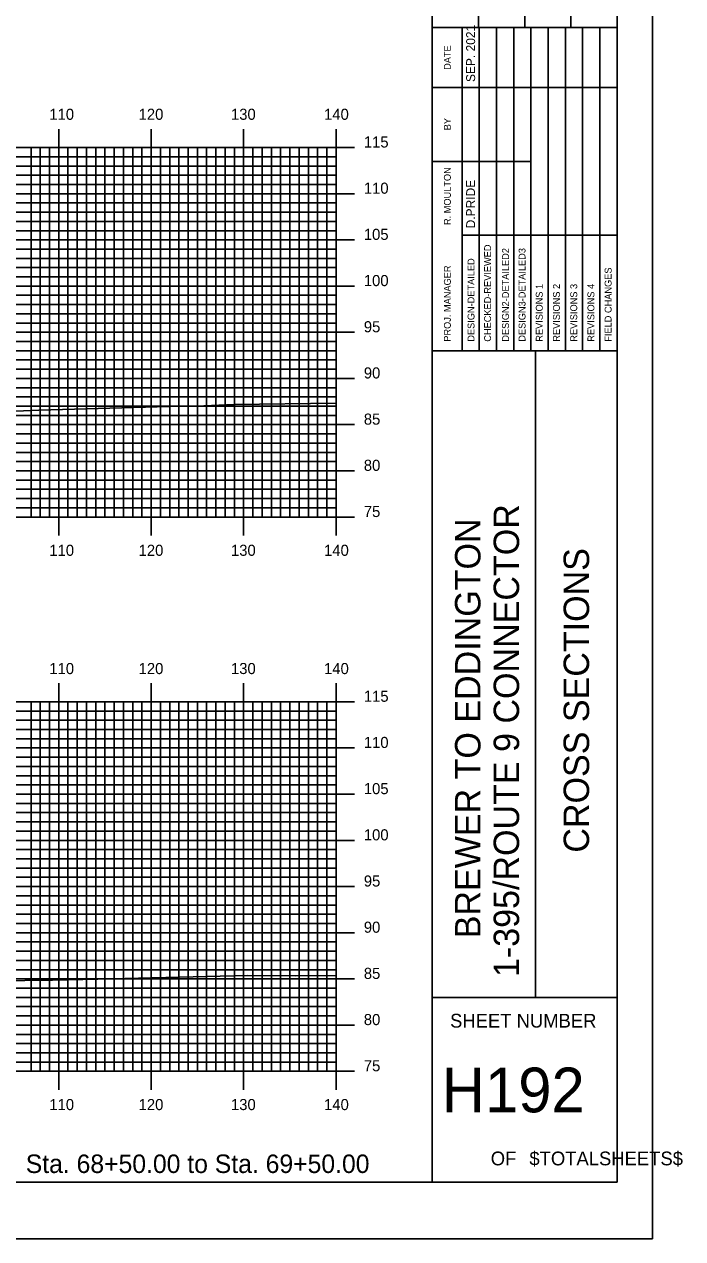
# Model space of a CAD drawing. Extents: x 1759823 to 1760167, y 442591 to 442811.
# Drawn here: x 1760095.5 to 1760166.7, y 442590.5 to 442722 of the extents above; entities that cross this region are included whole.
import ezdxf

# ---------------------------------------------------------------- set-up
doc = ezdxf.new("R2010")
doc.units = 0
for name, color, linetype in [('BORDER', 7, 'Continuous'), ('H_V ANNOTATION', 7, 'Continuous'), ('MAJOR', 7, 'Continuous'), ('MINOR', 7, 'Continuous'), ('PLOT BOUNDARY', 7, 'Continuous'), ('S_Roadway_Centerline', 7, 'Continuous')]:
    doc.layers.add(name, color=color, linetype=linetype)

msp = doc.modelspace()

# ---------------------------------------------------------------- linework, layer by layer
at = {"layer": 'BORDER'}
for p, q in [((1760139.59, 442596.67), (1760139.59, 442806.67)), ((1760144.59, 442721.67), (1760144.59, 442738.97)), ((1760149.59, 442721.67), (1760149.59, 442738.97)), ((1760154.59, 442721.67), (1760154.59, 442738.97)), ((1760139.59, 442721.67), (1760159.59, 442721.67)), ((1760139.59, 442686.67), (1760159.59, 442686.67)), ((1760150.77, 442616.67), (1760150.77, 442686.67)), ((1760139.59, 442616.67), (1760159.59, 442616.67))]:
    msp.add_line(p, q, dxfattribs=at)
msp.add_lwpolyline([(1759839.59, 442596.67), (1760159.59, 442596.67), (1760159.59, 442806.67), (1759839.59, 442806.67)], close=True, dxfattribs=at)
for points in [[(1760142.82, 442715.17), (1760142.82, 442721.67)], [(1760144.68, 442686.68), (1760144.68, 442721.67)], [(1760146.55, 442721.67), (1760146.55, 442686.68)], [(1760148.41, 442686.68), (1760148.41, 442721.67)], [(1760150.27, 442686.68), (1760150.27, 442721.67)], [(1760152.14, 442686.68), (1760152.14, 442721.67)], [(1760154, 442686.68), (1760154, 442721.67)], [(1760155.86, 442686.68), (1760155.86, 442721.67)], [(1760157.73, 442686.68), (1760157.73, 442721.67)], [(1760142.82, 442686.68), (1760142.82, 442720.26)], [(1760139.59, 442715.17), (1760159.59, 442715.17)], [(1760139.59, 442707.17), (1760142.82, 442707.17)], [(1760142.82, 442707.17), (1760150.27, 442707.17)], [(1760142.82, 442699.17), (1760159.59, 442699.17)]]:
    msp.add_lwpolyline(points, dxfattribs=at)
at = {"layer": 'MAJOR'}
for p, q in [((1760099.19, 442710.67), (1760099.19, 442708.67)), ((1760109.19, 442710.67), (1760109.19, 442708.67)), ((1760119.19, 442710.67), (1760119.19, 442708.67)), ((1760129.19, 442710.67), (1760129.19, 442708.67)), ((1759849.19, 442708.67), (1760129.19, 442708.67)), ((1759849.19, 442708.67), (1760129.19, 442708.67)), ((1760099.19, 442668.67), (1760099.19, 442708.67)), ((1760109.19, 442668.67), (1760109.19, 442708.67)), ((1760119.19, 442668.67), (1760119.19, 442708.67)), ((1760131.19, 442708.67), (1760127.18, 442708.67)), ((1760129.19, 442668.67), (1760129.19, 442708.67)), ((1760129.19, 442668.67), (1760129.19, 442708.67)), ((1759849.19, 442703.67), (1760129.19, 442703.67)), ((1760131.19, 442703.67), (1760127.18, 442703.67)), ((1759849.19, 442698.67), (1760129.19, 442698.67)), ((1760131.19, 442698.67), (1760127.18, 442698.67)), ((1759849.19, 442693.67), (1760129.19, 442693.67)), ((1760131.19, 442693.67), (1760127.18, 442693.67)), ((1759849.19, 442688.67), (1760129.19, 442688.67)), ((1760131.19, 442688.67), (1760127.18, 442688.67)), ((1759849.19, 442683.67), (1760129.19, 442683.67)), ((1760131.19, 442683.67), (1760127.18, 442683.67)), ((1759849.19, 442678.67), (1760129.19, 442678.67)), ((1760131.19, 442678.67), (1760127.18, 442678.67)), ((1759849.19, 442673.67), (1760129.19, 442673.67)), ((1760131.19, 442673.67), (1760127.18, 442673.67)), ((1759849.19, 442668.67), (1760129.19, 442668.67)), ((1759849.19, 442668.67), (1760129.19, 442668.67)), ((1760099.19, 442666.66), (1760099.19, 442668.67)), ((1760109.19, 442666.66), (1760109.19, 442668.67)), ((1760119.19, 442666.66), (1760119.19, 442668.67)), ((1760131.19, 442668.67), (1760127.18, 442668.67)), ((1760129.19, 442666.66), (1760129.19, 442668.67)), ((1760099.19, 442650.67), (1760099.19, 442648.67)), ((1760109.19, 442650.67), (1760109.19, 442648.67)), ((1760119.19, 442650.67), (1760119.19, 442648.67)), ((1760129.19, 442650.67), (1760129.19, 442648.67)), ((1759849.19, 442648.67), (1760129.19, 442648.67)), ((1759849.19, 442648.67), (1760129.19, 442648.67)), ((1760099.19, 442608.67), (1760099.19, 442648.67)), ((1760109.19, 442608.67), (1760109.19, 442648.67)), ((1760119.19, 442608.67), (1760119.19, 442648.67)), ((1760131.19, 442648.67), (1760127.18, 442648.67)), ((1760129.19, 442608.67), (1760129.19, 442648.67)), ((1760129.19, 442608.67), (1760129.19, 442648.67)), ((1759849.19, 442643.67), (1760129.19, 442643.67)), ((1760131.19, 442643.67), (1760127.18, 442643.67)), ((1759849.19, 442638.67), (1760129.19, 442638.67)), ((1760131.19, 442638.67), (1760127.18, 442638.67)), ((1759849.19, 442633.67), (1760129.19, 442633.67)), ((1760131.19, 442633.67), (1760127.18, 442633.67)), ((1759849.19, 442628.67), (1760129.19, 442628.67)), ((1760131.19, 442628.67), (1760127.18, 442628.67)), ((1759849.19, 442623.67), (1760129.19, 442623.67)), ((1760131.19, 442623.67), (1760127.18, 442623.67)), ((1759849.19, 442618.67), (1760129.19, 442618.67)), ((1760131.19, 442618.67), (1760127.18, 442618.67)), ((1759849.19, 442613.67), (1760129.19, 442613.67)), ((1760131.19, 442613.67), (1760127.18, 442613.67)), ((1759849.19, 442608.67), (1760129.19, 442608.67)), ((1759849.19, 442608.67), (1760129.19, 442608.67)), ((1760099.19, 442606.66), (1760099.19, 442608.67)), ((1760109.19, 442606.66), (1760109.19, 442608.67)), ((1760119.19, 442606.66), (1760119.19, 442608.67)), ((1760131.19, 442608.67), (1760127.18, 442608.67)), ((1760129.19, 442606.66), (1760129.19, 442608.67))]:
    msp.add_line(p, q, dxfattribs=at)
at = {"layer": 'MINOR'}
for p, q in [((1760096.19, 442668.67), (1760096.19, 442708.67)), ((1760097.19, 442668.67), (1760097.19, 442708.67)), ((1760098.19, 442668.67), (1760098.19, 442708.67)), ((1760100.19, 442668.67), (1760100.19, 442708.67)), ((1760101.19, 442668.67), (1760101.19, 442708.67)), ((1760102.19, 442668.67), (1760102.19, 442708.67)), ((1760103.19, 442668.67), (1760103.19, 442708.67)), ((1760104.19, 442668.67), (1760104.19, 442708.67)), ((1760105.19, 442668.67), (1760105.19, 442708.67)), ((1760106.19, 442668.67), (1760106.19, 442708.67)), ((1760107.19, 442668.67), (1760107.19, 442708.67)), ((1760108.19, 442668.67), (1760108.19, 442708.67)), ((1760110.19, 442668.67), (1760110.19, 442708.67)), ((1760111.19, 442668.67), (1760111.19, 442708.67)), ((1760112.19, 442668.67), (1760112.19, 442708.67)), ((1760113.19, 442668.67), (1760113.19, 442708.67)), ((1760114.19, 442668.67), (1760114.19, 442708.67)), ((1760115.19, 442668.67), (1760115.19, 442708.67)), ((1760116.19, 442668.67), (1760116.19, 442708.67)), ((1760117.19, 442668.67), (1760117.19, 442708.67)), ((1760118.19, 442668.67), (1760118.19, 442708.67)), ((1760120.19, 442668.67), (1760120.19, 442708.67)), ((1760121.19, 442668.67), (1760121.19, 442708.67)), ((1760122.19, 442668.67), (1760122.19, 442708.67)), ((1760123.19, 442668.67), (1760123.19, 442708.67)), ((1760124.19, 442668.67), (1760124.19, 442708.67)), ((1760125.19, 442668.67), (1760125.19, 442708.67)), ((1760126.19, 442668.67), (1760126.19, 442708.67)), ((1760127.19, 442668.67), (1760127.19, 442708.67)), ((1760128.19, 442668.67), (1760128.19, 442708.67)), ((1759849.19, 442707.67), (1760129.19, 442707.67)), ((1760129.19, 442707.67), (1760127.18, 442707.67)), ((1759849.19, 442706.67), (1760129.19, 442706.67)), ((1759849.19, 442705.67), (1760129.19, 442705.67)), ((1760129.19, 442706.67), (1760127.18, 442706.67)), ((1760129.19, 442705.67), (1760127.18, 442705.67)), ((1759849.19, 442704.67), (1760129.19, 442704.67)), ((1760129.19, 442704.67), (1760127.18, 442704.67)), ((1759849.19, 442702.67), (1760129.19, 442702.67)), ((1759849.19, 442701.67), (1760129.19, 442701.67)), ((1760129.19, 442702.67), (1760127.18, 442702.67)), ((1760129.19, 442701.67), (1760127.18, 442701.67)), ((1759849.19, 442700.67), (1760129.19, 442700.67)), ((1760129.19, 442700.67), (1760127.18, 442700.67)), ((1759849.19, 442699.67), (1760129.19, 442699.67)), ((1760129.19, 442699.67), (1760127.18, 442699.67)), ((1759849.19, 442697.67), (1760129.19, 442697.67)), ((1760129.19, 442697.67), (1760127.18, 442697.67)), ((1759849.19, 442696.67), (1760129.19, 442696.67)), ((1760129.19, 442696.67), (1760127.18, 442696.67)), ((1759849.19, 442695.67), (1760129.19, 442695.67)), ((1760129.19, 442695.67), (1760127.18, 442695.67)), ((1759849.19, 442694.67), (1760129.19, 442694.67)), ((1760129.19, 442694.67), (1760127.18, 442694.67)), ((1759849.19, 442692.67), (1760129.19, 442692.67)), ((1760129.19, 442692.67), (1760127.18, 442692.67)), ((1759849.19, 442691.67), (1760129.19, 442691.67)), ((1760129.19, 442691.67), (1760127.18, 442691.67)), ((1759849.19, 442690.67), (1760129.19, 442690.67)), ((1760129.19, 442690.67), (1760127.18, 442690.67)), ((1759849.19, 442689.67), (1760129.19, 442689.67)), ((1760129.19, 442689.67), (1760127.18, 442689.67)), ((1759849.19, 442687.67), (1760129.19, 442687.67)), ((1760129.19, 442687.67), (1760127.18, 442687.67)), ((1759849.19, 442686.67), (1760129.19, 442686.67)), ((1760129.19, 442686.67), (1760127.18, 442686.67)), ((1759849.19, 442685.67), (1760129.19, 442685.67)), ((1759849.19, 442684.67), (1760129.19, 442684.67)), ((1760129.19, 442685.67), (1760127.18, 442685.67)), ((1760129.19, 442684.67), (1760127.18, 442684.67)), ((1759849.19, 442682.67), (1760129.19, 442682.67)), ((1760129.19, 442682.67), (1760127.18, 442682.67)), ((1759849.19, 442681.67), (1760129.19, 442681.67)), ((1759849.19, 442680.67), (1760129.19, 442680.67)), ((1760129.19, 442681.67), (1760127.18, 442681.67)), ((1760129.19, 442680.67), (1760127.18, 442680.67)), ((1759849.19, 442679.67), (1760129.19, 442679.67)), ((1760129.19, 442679.67), (1760127.18, 442679.67)), ((1759849.19, 442677.67), (1760129.19, 442677.67)), ((1759849.19, 442676.67), (1760129.19, 442676.67)), ((1760129.19, 442677.67), (1760127.18, 442677.67)), ((1760129.19, 442676.67), (1760127.18, 442676.67)), ((1759849.19, 442675.67), (1760129.19, 442675.67)), ((1760129.19, 442675.67), (1760127.18, 442675.67)), ((1759849.19, 442674.67), (1760129.19, 442674.67)), ((1760129.19, 442674.67), (1760127.18, 442674.67)), ((1759849.19, 442672.67), (1760129.19, 442672.67)), ((1760129.19, 442672.67), (1760127.18, 442672.67)), ((1759849.19, 442671.67), (1760129.19, 442671.67)), ((1760129.19, 442671.67), (1760127.18, 442671.67)), ((1759849.19, 442670.67), (1760129.19, 442670.67)), ((1760129.19, 442670.67), (1760127.18, 442670.67)), ((1759849.19, 442669.67), (1760129.19, 442669.67)), ((1760129.19, 442669.67), (1760127.18, 442669.67)), ((1759849.19, 442647.67), (1760129.19, 442647.67)), ((1760096.19, 442608.67), (1760096.19, 442648.67)), ((1760097.19, 442608.67), (1760097.19, 442648.67)), ((1760098.19, 442608.67), (1760098.19, 442648.67)), ((1760100.19, 442608.67), (1760100.19, 442648.67)), ((1760101.19, 442608.67), (1760101.19, 442648.67)), ((1760102.19, 442608.67), (1760102.19, 442648.67)), ((1760103.19, 442608.67), (1760103.19, 442648.67)), ((1760104.19, 442608.67), (1760104.19, 442648.67)), ((1760105.19, 442608.67), (1760105.19, 442648.67)), ((1760106.19, 442608.67), (1760106.19, 442648.67)), ((1760107.19, 442608.67), (1760107.19, 442648.67)), ((1760108.19, 442608.67), (1760108.19, 442648.67)), ((1760110.19, 442608.67), (1760110.19, 442648.67)), ((1760111.19, 442608.67), (1760111.19, 442648.67)), ((1760112.19, 442608.67), (1760112.19, 442648.67)), ((1760113.19, 442608.67), (1760113.19, 442648.67)), ((1760114.19, 442608.67), (1760114.19, 442648.67)), ((1760115.19, 442608.67), (1760115.19, 442648.67)), ((1760116.19, 442608.67), (1760116.19, 442648.67)), ((1760117.19, 442608.67), (1760117.19, 442648.67)), ((1760118.19, 442608.67), (1760118.19, 442648.67)), ((1760120.19, 442608.67), (1760120.19, 442648.67)), ((1760121.19, 442608.67), (1760121.19, 442648.67)), ((1760122.19, 442608.67), (1760122.19, 442648.67)), ((1760123.19, 442608.67), (1760123.19, 442648.67)), ((1760124.19, 442608.67), (1760124.19, 442648.67)), ((1760125.19, 442608.67), (1760125.19, 442648.67)), ((1760126.19, 442608.67), (1760126.19, 442648.67)), ((1760129.19, 442647.67), (1760127.18, 442647.67)), ((1760127.19, 442608.67), (1760127.19, 442648.67)), ((1760128.19, 442608.67), (1760128.19, 442648.67)), ((1759849.19, 442646.67), (1760129.19, 442646.67)), ((1760129.19, 442646.67), (1760127.18, 442646.67)), ((1759849.19, 442645.67), (1760129.19, 442645.67)), ((1760129.19, 442645.67), (1760127.18, 442645.67)), ((1759849.19, 442644.67), (1760129.19, 442644.67)), ((1760129.19, 442644.67), (1760127.18, 442644.67)), ((1759849.19, 442642.67), (1760129.19, 442642.67)), ((1760129.19, 442642.67), (1760127.18, 442642.67)), ((1759849.19, 442641.67), (1760129.19, 442641.67)), ((1760129.19, 442641.67), (1760127.18, 442641.67)), ((1759849.19, 442640.67), (1760129.19, 442640.67)), ((1760129.19, 442640.67), (1760127.18, 442640.67)), ((1759849.19, 442639.67), (1760129.19, 442639.67)), ((1760129.19, 442639.67), (1760127.18, 442639.67)), ((1759849.19, 442637.67), (1760129.19, 442637.67)), ((1760129.19, 442637.67), (1760127.18, 442637.67)), ((1759849.19, 442636.67), (1760129.19, 442636.67)), ((1760129.19, 442636.67), (1760127.18, 442636.67)), ((1759849.19, 442635.67), (1760129.19, 442635.67)), ((1759849.19, 442634.67), (1760129.19, 442634.67)), ((1760129.19, 442635.67), (1760127.18, 442635.67)), ((1760129.19, 442634.67), (1760127.18, 442634.67)), ((1759849.19, 442632.67), (1760129.19, 442632.67)), ((1760129.19, 442632.67), (1760127.18, 442632.67)), ((1759849.19, 442631.67), (1760129.19, 442631.67)), ((1759849.19, 442630.67), (1760129.19, 442630.67)), ((1760129.19, 442631.67), (1760127.18, 442631.67)), ((1760129.19, 442630.67), (1760127.18, 442630.67)), ((1759849.19, 442629.67), (1760129.19, 442629.67)), ((1760129.19, 442629.67), (1760127.18, 442629.67)), ((1759849.19, 442627.67), (1760129.19, 442627.67)), ((1759849.19, 442626.67), (1760129.19, 442626.67)), ((1760129.19, 442627.67), (1760127.18, 442627.67)), ((1760129.19, 442626.67), (1760127.18, 442626.67)), ((1759849.19, 442625.67), (1760129.19, 442625.67)), ((1760129.19, 442625.67), (1760127.18, 442625.67)), ((1759849.19, 442624.67), (1760129.19, 442624.67)), ((1760129.19, 442624.67), (1760127.18, 442624.67)), ((1759849.19, 442622.67), (1760129.19, 442622.67)), ((1760129.19, 442622.67), (1760127.18, 442622.67)), ((1759849.19, 442621.67), (1760129.19, 442621.67)), ((1760129.19, 442621.67), (1760127.18, 442621.67)), ((1759849.19, 442620.67), (1760129.19, 442620.67)), ((1760129.19, 442620.67), (1760127.18, 442620.67)), ((1759849.19, 442619.67), (1760129.19, 442619.67)), ((1760129.19, 442619.67), (1760127.18, 442619.67)), ((1759849.19, 442617.67), (1760129.19, 442617.67)), ((1760129.19, 442617.67), (1760127.18, 442617.67)), ((1759849.19, 442616.67), (1760129.19, 442616.67)), ((1760129.19, 442616.67), (1760127.18, 442616.67)), ((1759849.19, 442615.67), (1760129.19, 442615.67)), ((1760129.19, 442615.67), (1760127.18, 442615.67)), ((1759849.19, 442614.67), (1760129.19, 442614.67)), ((1760129.19, 442614.67), (1760127.18, 442614.67)), ((1759849.19, 442612.67), (1760129.19, 442612.67)), ((1760129.19, 442612.67), (1760127.18, 442612.67)), ((1759849.19, 442611.67), (1760129.19, 442611.67)), ((1760129.19, 442611.67), (1760127.18, 442611.67)), ((1759849.19, 442610.67), (1760129.19, 442610.67)), ((1759849.19, 442609.67), (1760129.19, 442609.67)), ((1760129.19, 442610.67), (1760127.18, 442610.67)), ((1760129.19, 442609.67), (1760127.18, 442609.67))]:
    msp.add_line(p, q, dxfattribs=at)
at = {"layer": 'PLOT BOUNDARY'}
msp.add_lwpolyline([(1759823.4, 442590.55), (1760163.4, 442590.55), (1760163.4, 442810.55), (1759823.4, 442810.55)], close=True, dxfattribs=at)
at = {"layer": 'S_Roadway_Centerline'}
for points in [[(1760021.92, 442677.99), (1760032.85, 442678.42), (1760033.94, 442678.46), (1760034.82, 442678.49), (1760045.31, 442678.69), (1760055.22, 442679.36), (1760059.66, 442679.52), (1760076.74, 442679.65), (1760080.19, 442679.7), (1760085.5, 442679.88), (1760092.06, 442680.03), (1760097.04, 442680.25), (1760111.13, 442680.63), (1760114.9, 442680.71), (1760118.12, 442680.84), (1760129.19, 442680.98)], [(1760018.12, 442616.64), (1760028.47, 442616.89), (1760036.49, 442617.09), (1760044, 442617.36), (1760056.97, 442617.66), (1760063.01, 442617.61), (1760071.47, 442617.83), (1760077.81, 442618.21), (1760097.71, 442618.55), (1760098.53, 442618.52), (1760103.41, 442618.63), (1760119.61, 442619.04), (1760124.83, 442618.99), (1760129.19, 442619.03)]]:
    msp.add_lwpolyline(points, dxfattribs=at)

# ---------------------------------------------------------------- texts
at = {"layer": 'BORDER'}
for s, height, p in [('SEP. 2021', 0.969, (1760144.23, 442715.76)), ('DATE', 0.743, (1760141.6, 442717.08)), ('BY', 0.743, (1760141.6, 442710.54)), ('R. MOULTON', 0.745, (1760141.6, 442700.28)), ('D.PRIDE', 0.969, (1760144.23, 442699.92)), ('CHECKED-REVIEWED', 0.7455, (1760145.95, 442687.65)), ('DESIGN2-DETAILED2', 0.7455, (1760147.89, 442687.65)), ('DESIGN3-DETAILED3', 0.7455, (1760149.68, 442687.65)), ('DESIGN-DETAILED', 0.7455, (1760144.16, 442687.65)), ('PROJ. MANAGER', 0.7455, (1760141.6, 442687.65)), ('FIELD CHANGES', 0.7455, (1760158.99, 442687.65)), ('REVISIONS 1', 0.7455, (1760151.54, 442687.65)), ('REVISIONS 2', 0.7455, (1760153.4, 442687.65)), ('REVISIONS 3', 0.7455, (1760155.27, 442687.65)), ('REVISIONS 4', 0.7455, (1760157.13, 442687.65)), ('1-395/ROUTE 9 CONNECTOR', 2.7557, (1760148.99, 442618.87)), ('BREWER TO EDDINGTON', 2.7557, (1760144.81, 442623.07)), ('CROSS SECTIONS', 2.7557, (1760156.56, 442632.34))]:
    msp.add_text(s, height=height, rotation=90, dxfattribs=at).set_placement(p)
for s, height, p in [('SHEET NUMBER', 1.4905, (1760141.52, 442613.4)), ('H192', 4.839, (1760140.62, 442604.23)), ('OF', 1.491, (1760145.92, 442598.49)), ('$TOTALSHEETS$', 1.4905, (1760150.1, 442598.49))]:
    msp.add_text(s, height=height, dxfattribs=at).set_placement(p)
at = {"layer": 'H_V ANNOTATION'}
for s, height, p in [('110', 1.2, (1760098.17, 442711.67)), ('120', 1.2, (1760107.83, 442711.67)), ('130', 1.2, (1760117.82, 442711.67)), ('140', 1.2, (1760127.89, 442711.67)), ('115', 1.2, (1760132.19, 442708.67)), ('110', 1.2, (1760132.19, 442703.67)), ('105', 1.2, (1760132.19, 442698.67)), ('100', 1.2, (1760132.19, 442693.67)), ('95', 1.2, (1760132.19, 442688.67)), ('90', 1.2, (1760132.19, 442683.67)), ('85', 1.2, (1760132.19, 442678.67)), ('80', 1.2, (1760132.19, 442673.67)), ('75', 1.2, (1760132.19, 442668.67)), ('110', 1.2, (1760098.17, 442664.47)), ('120', 1.2, (1760107.83, 442664.47)), ('130', 1.2, (1760117.82, 442664.47)), ('140', 1.2, (1760127.89, 442664.47)), ('110', 1.2, (1760098.17, 442651.67)), ('120', 1.2, (1760107.83, 442651.67)), ('130', 1.2, (1760117.82, 442651.67)), ('140', 1.2, (1760127.89, 442651.67)), ('115', 1.2, (1760132.19, 442648.67)), ('110', 1.2, (1760132.19, 442643.67)), ('105', 1.2, (1760132.19, 442638.67)), ('100', 1.2, (1760132.19, 442633.67)), ('95', 1.2, (1760132.19, 442628.67)), ('90', 1.2, (1760132.19, 442623.67)), ('85', 1.2, (1760132.19, 442618.67)), ('80', 1.2, (1760132.19, 442613.67)), ('75', 1.2, (1760132.19, 442608.67)), ('110', 1.2, (1760098.17, 442604.47)), ('120', 1.2, (1760107.83, 442604.47)), ('130', 1.2, (1760117.82, 442604.47)), ('140', 1.2, (1760127.89, 442604.47)), ('Sta. 68+50.00 to Sta. 69+50.00', 2.0004, (1760095.62, 442597.66))]:
    msp.add_text(s, height=height, dxfattribs=at).set_placement(p)

doc.saveas('drawing.dxf')
